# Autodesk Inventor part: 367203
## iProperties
Created: 2006-08
Part Number: 367203
Material: 8.8 vz
Description: Zylinderschraube
Vendor: Autodesk Inc.
Document SubType Name: Modeling
Standard: DIN 912
Designer: I.Baliuc
Standards Organization: DIN
Language: de-DE
Size Designation: M5 x 16
Categories: <MemberInstance Version="R10.0.0"><Categories><Category DisplayName="Schrauben" InternalName="e4da775c-781d-43d5-af7c-5136215cf5a6" Mnemonic="FSTN"><Category Di
Density: 7.85 g/cm^3
Mass: 4.30811 g
Surface Area: 5.20012 cm^2
Volume: 0.548803 cm^3
Abmessung: M5 x 16
Author: T.Messerschmitt
Comments: DIN 912 - M5 x 16
Revision Number: 367203
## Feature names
1. Körper [Revolution]
2. Loch [Extrusion]
3. Rundung1 [Fillet]
4. Fase1 [Chamfer]
